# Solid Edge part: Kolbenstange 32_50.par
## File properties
Username: ahadarics
Dokumentum tartalom típus: 0
Author: ahadarics
Last saved by: ahadarics
Revision: 79
Sűrűség: 0,000 kg/m^3
Pontosság: 0,990
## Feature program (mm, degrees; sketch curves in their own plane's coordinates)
base feature "unnamed BaseFeature 1"
thread "unnamed Thread 1"
chamfer "Letörés_1"  SetBackValue2 = 20 deg
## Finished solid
Body 1: solid body, 19 faces, 27 edges, 11 vertices.
  Faces by surface: plane 8, cylinder 5, cone 3, torus 3
  Edges by curve: circle 15, line 7, curve on surface 3, ellipse 2
Bounding box of the edges (mm; curved faces can reach further): 32.000 x 32.000 x 165.500, from (-16, -16, -50.25) to (16, 16, 115.25).
Cylindrical faces by radius (mm): R3.95 x1, R5 x1, R5.8 x1, R6 x1, R16 x1
Conical faces (half-angle, radius in mm at the cone's reference point): 20 deg R5 x1, 30 deg R5.9 x1, 60 deg R4.475 x1
Toroidal faces (ring radius, tube radius in mm): R4.35 r0.4 x2, R4.6 r1.2 x1
Planar faces by outward normal: +x 1, +z 3, -x 1, -z 1, oblique 2
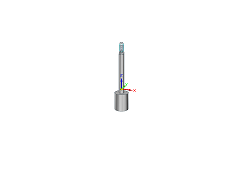
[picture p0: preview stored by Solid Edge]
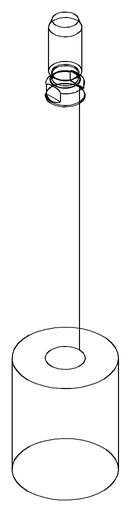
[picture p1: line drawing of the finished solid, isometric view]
